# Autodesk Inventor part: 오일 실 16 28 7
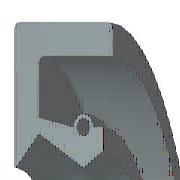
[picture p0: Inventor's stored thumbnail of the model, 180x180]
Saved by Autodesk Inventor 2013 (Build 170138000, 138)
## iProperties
Created: 2012-02
Part Number: 오일 실 16 28 7
Material: 고무
Description: 오일-실
Document SubType Name: Modeling
Standard: KS B 2804
Designer: mduedu
Standards Organization: KS
Language: ko-KR
Size Designation: D - 16 28 7
Categories: <MemberInstance><Categories><Category DisplayName="샤프트 부품" InternalName="7f7aeb1f-a693-4053-b835-cee3144e0d98" Mnemonic="SHFT"><Category DisplayName="실링" Intern
Density: 0.93 g/cm^3
IsCustomPart: 1
Author: mduedu
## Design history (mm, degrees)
revolve "본체" stored, may be unused: angle "d17" = 90 deg
revolve "스프링1" stored, may be unused: angle "d18" = 90 deg
fillet "모깎기3" dims "d43" = 0.5
body "Solid1"
sketch "스케치1"
  geometry: L1 (0, 14)-(7, 14); L2 (7, 12.25)-(1.75, 12.25); L3 (1.75, 9.75)-(4.9, 8); L4 (4.9, 8)-(0, 8); L5 (0, 0)-(9.586, 0) reference; L6 (4.9, 8)-(6.3, 8.875); L7 (0, 18)-(0, -3) reference; L8 (-1.941, 0)-(11.507, 0) reference; L9 (4.2, 10.1)-(1.75, 10.59); L10 (1.75, 10.59)-(1.75, 12.25); L11 (0, 14)-(0, 8.088); L12 (4.9, 8)-(0, 8); L13 (1.75, 9.75)-(0.152, 8.028); L14 (7, 14)-(7, 12.25); L15 (5.6, 10.1)-(6.3, 10.1); L16 (6.3, 10.1)-(6.3, 8.875); C1 r 0.455 at (4.9, 10.1); A1 r 0.7 centre (4.9, 10.1) between (5.6, 10.1) and (4.2, 10.1); A2 r 0.088 centre (0.088, 8.088) between (0, 8.088) and (0.152, 8.028); 1 further point
  constraints: 28 end point, 5 horizontal alignment, 5 point on line, 4 point on circle, 4 vertical alignment, 3 centre point, 3 tangent, 2 collinear, 2 horizontal, 2 perpendicular, 1 coincident, 1 parallel
  dimensions: "d0" = 28 diameter of L1 L5 (= SD2); "d1" = 1.75 distance of L1.end L2.start (= SD); "d2" = 0.91 diameter of C1 (= SPDI); "d3" = 1.4 diameter of A1 (= SPDA); "d4" = 16 diameter of L3.end L5 (= NND); "d5" = 19.5 diameter of L3.start L5 (= TKDM); "d7" = 21.18 diameter of L9.end L5 (= TKDM + 0.24 x SWDT); "d8" = 1.75 distance between parallel lines of L11 L10 (= SD); "d9" = 4.9 distance from line of L11 C1.centre (= SPDST); "d10" = 20.2 diameter of C1.centre L5 (= HLDM); "d11" = 0.0875 radius of A2 (= 0.25 x LAB); "d12" = 6.3 distance between parallel lines of L11 L16 (= SDI); "d13" = 17.75 diameter of L6.end L5 (= ABDM); "d14" = 7 distance from line of L11 L1.end (= SWDT)
fillet "모깎기1" dims "d6" = 0.3 (= RR)
other parameters: "SD2" = 28 [user parameter; used in 1 equation term], "SWDT" = 7 [user parameter; used in 2 equation terms], "RR" = 0.3 [user parameter; used in 1 equation term], "SD" = 1.75 [user parameter; used in 2 equation terms], "NND" = 16 [user parameter; used in 1 equation term], "SPDA" = 1.4 [user parameter; used in 1 equation term], "SPDI" = 0.91 [user parameter; used in 1 equation term], "TKDM" = 19.5 [user parameter; used in 2 equation terms], "HLDM" = 20.2 [user parameter; used in 1 equation term], "ABDM" = 17.75 [user parameter; used in 1 equation term], "SDI" = 6.3 [user parameter; used in 1 equation term], "SPDST" = 4.9 [user parameter; used in 1 equation term], "LAB" = 0.35 [user parameter; used in 1 equation term], "d15" = 0, "d16" = 0, "d19" = 0
